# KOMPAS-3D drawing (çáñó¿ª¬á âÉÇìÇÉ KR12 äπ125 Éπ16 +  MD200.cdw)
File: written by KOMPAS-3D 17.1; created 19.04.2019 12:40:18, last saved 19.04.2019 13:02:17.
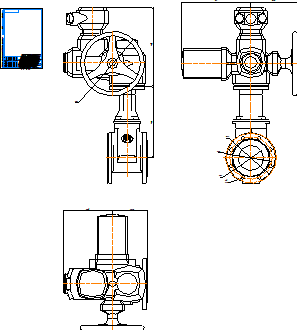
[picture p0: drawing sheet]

Sheet 1: A4, portrait

Title block, sheet 1: name: Задвижка ГРАНАР KR12 Ду125 Ру16 + / MD200; material: Внимание! Данный продукт является объектом авторского права ООО «Торговый Дом АДЛ». / Запрещается изменение, копирование, распространение / (в том числе путем копирования на другие сайты и ресурсы в Интернете) / или любое иное использование информации и объектов без предварительного / согласия правообладателя (ООО «Торговый Дом АДЛ»).; mass: 199,64; sheets: 1; organisation: ООО "Торговый дом АДЛ"; sheet format: A4; stored path: \\adlc.lan\data\АДЛ_ПКД\3D-модели\ADL production\Клиновые задвижки серии KR ГРАНАР\Клиновые задвижки KR12 с эл.приводами Смартгир\KOMPAS 2D\Задвижка ГРАНАР KR12 Ду125 Ру16 +  MD200.cdw

Views: Проекционный вид 3
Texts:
  user
Dimensions and other numbers on the sheet: 250; 210; 241,19; 173,81; 1:1; 1; 199,64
